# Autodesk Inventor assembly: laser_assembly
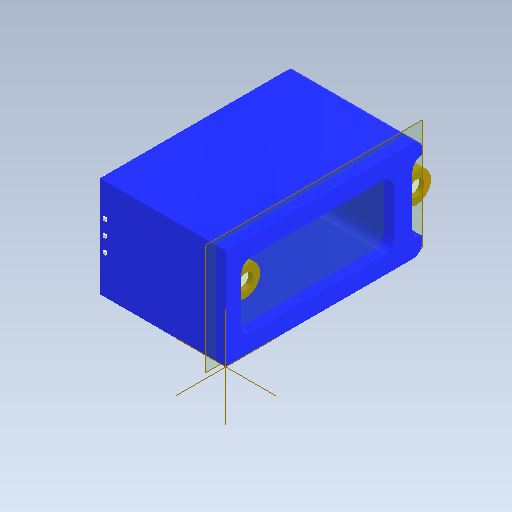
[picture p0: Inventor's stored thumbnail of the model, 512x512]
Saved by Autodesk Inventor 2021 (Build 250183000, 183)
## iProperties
Created: 2026-10
Part Number: laser_assembly
Document SubType Name: Assembly
Designer: alolo
Author: alolo
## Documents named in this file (3)
- C:\Users\alolo\Documents\Inventor\Design 1\laser_assembly.iam
- C:\Users\alolo\Documents\Inventor\Design 1\laser_rack.ipt
- C:\Users\alolo\Documents\Inventor\Design 1\650nm Laser Transmitter Module (KY-008).ipt
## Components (3 placed, 2 different names)
1. laser_rack:1 — Mate:1, Mate:2, Mate:3, Mate:4, Mate:5, Mate:6, Mate:7, Angle:1
2. 650nm Laser Transmitter Module (KY-008):1 — Mate:3, Mate:4, Mate:9
3. 650nm Laser Transmitter Module (KY-008):2 — Mate:5, Mate:6, Mate:8
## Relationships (10: Mate 9, Angle 1)
- Mate:1: laser_rack:1
- Mate:2: laser_rack:1
- Mate:3: laser_rack:1 ↔ 650nm Laser Transmitter Module (KY-008):1
- Mate:4: laser_rack:1 ↔ 650nm Laser Transmitter Module (KY-008):1
- Mate:5: laser_rack:1 ↔ 650nm Laser Transmitter Module (KY-008):2
- Mate:6: laser_rack:1 ↔ 650nm Laser Transmitter Module (KY-008):2
- Mate:7: laser_rack:1
- Angle:1: laser_rack:1
- Mate:8: 650nm Laser Transmitter Module (KY-008):2
- Mate:9: 650nm Laser Transmitter Module (KY-008):1
